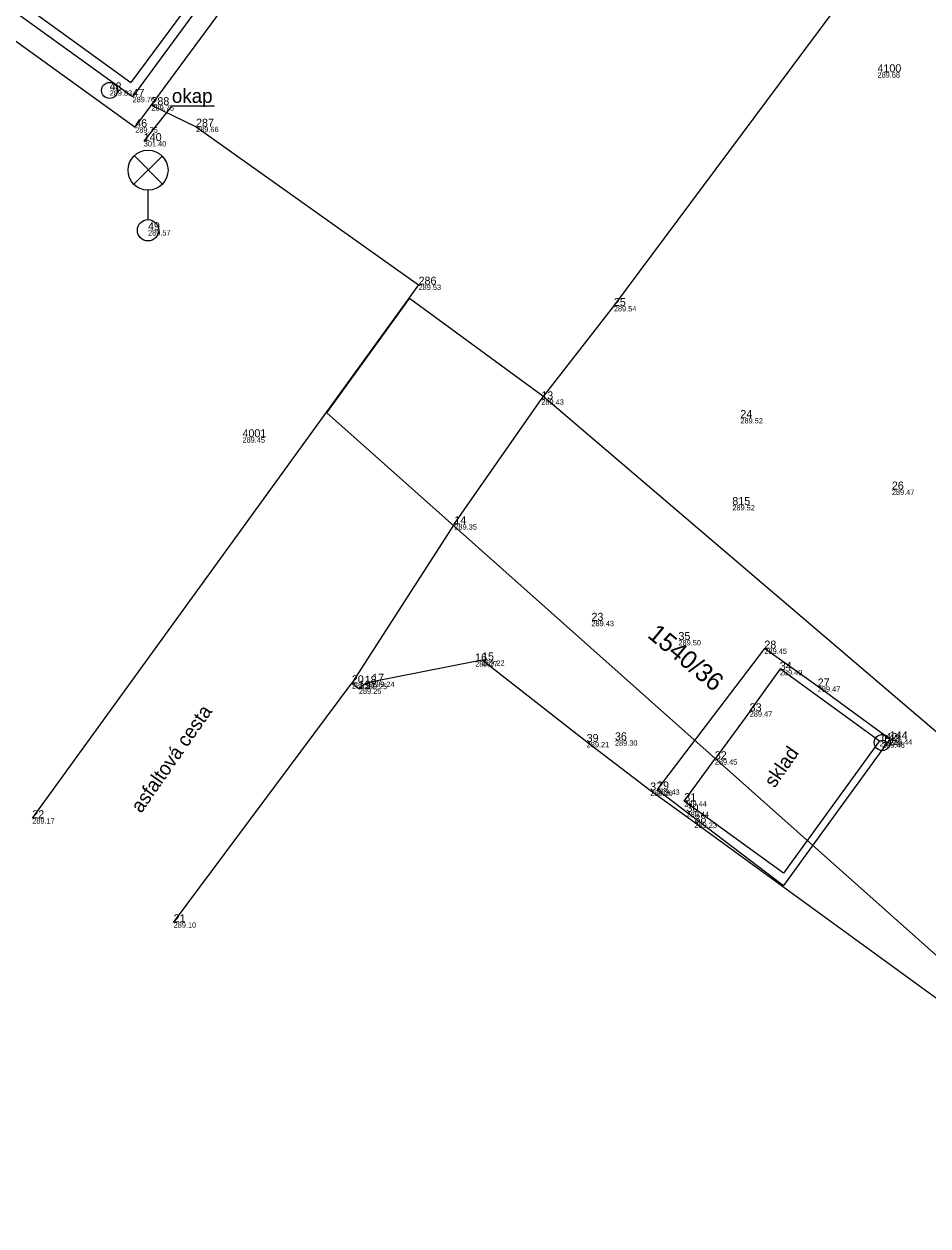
# Model space of a CAD drawing. Extents: x -805057 to -804930, y -994399 to -994240.
# Drawn here: x -804997.54 to -804980.6, y -994365.12 to -994342.6 of the extents above; entities that cross this region are included whole.
import ezdxf

# ---------------------------------------------------------------- set-up
doc = ezdxf.new("R2010")
doc.units = 0
for name, color, linetype in [('bod cislo', 7, 'Continuous'), ('bod pozice', 7, 'Continuous'), ('bod výška', 7, 'Continuous'), ('budova', 7, 'Continuous'), ('Katastralni mapa', 7, 'Continuous'), ('komunikace', 7, 'Continuous'), ('lampa', 7, 'Continuous'), ('plot', 7, 'Continuous'), ('popis', 7, 'Continuous'), ('svod', 7, 'Continuous')]:
    doc.layers.add(name, color=color, linetype=linetype)

msp = doc.modelspace()

# ---------------------------------------------------------------- linework, layer by layer
at = {"layer": 'bod pozice'}
for p, q in [((-804981.55, -994343.5), (-804981.55, -994343.5)), ((-804995.94, -994343.84), (-804995.94, -994343.84)), ((-804995.51, -994343.96), (-804995.51, -994343.96)), ((-804995.156, -994344.117), (-804995.156, -994344.117)), ((-804995.46, -994344.53), (-804995.46, -994344.53)), ((-804994.32, -994344.52), (-804994.32, -994344.52)), ((-804995.3, -994344.79), (-804995.3, -994344.79)), ((-804995.22, -994346.46), (-804995.22, -994346.46)), ((-804990.15, -994347.48), (-804990.15, -994347.48)), ((-804986.49, -994347.88), (-804986.49, -994347.88)), ((-804987.85, -994349.63), (-804987.85, -994349.63)), ((-804984.12, -994349.98), (-804984.12, -994349.98)), ((-804993.45, -994350.34), (-804993.45, -994350.34)), ((-804981.28, -994351.32), (-804981.28, -994351.32)), ((-804984.27, -994351.61), (-804984.27, -994351.61)), ((-804989.48, -994351.97), (-804989.48, -994351.97)), ((-804986.91, -994353.78), (-804986.91, -994353.78)), ((-804985.28, -994354.14), (-804985.28, -994354.14)), ((-804983.67, -994354.3), (-804983.67, -994354.3)), ((-804989.09, -994354.54), (-804989.09, -994354.54)), ((-804988.96, -994354.52), (-804988.96, -994354.52)), ((-804983.38, -994354.7), (-804983.38, -994354.7)), ((-804991.4, -994354.95), (-804991.4, -994354.95)), ((-804991.27, -994355.05), (-804991.27, -994355.05)), ((-804991.16, -994354.96), (-804991.16, -994354.96)), ((-804991.02, -994354.92), (-804991.02, -994354.92)), ((-804982.67, -994355.01), (-804982.67, -994355.01)), ((-804983.945, -994355.476), (-804983.945, -994355.476)), ((-804987, -994356.05), (-804987, -994356.05)), ((-804986.47, -994356.02), (-804986.47, -994356.02)), ((-804981.51, -994356.03), (-804981.51, -994356.03)), ((-804981.46, -994356.06), (-804981.46, -994356.06)), ((-804981.32, -994356), (-804981.32, -994356)), ((-804984.598, -994356.374), (-804984.598, -994356.374)), ((-804985.81, -994356.96), (-804985.81, -994356.96)), ((-804985.68, -994356.94), (-804985.68, -994356.94)), ((-804985.17, -994357.16), (-804985.17, -994357.16)), ((-804997.39, -994357.48), (-804997.39, -994357.48)), ((-804985.129, -994357.359), (-804985.129, -994357.359)), ((-804984.98, -994357.56), (-804984.98, -994357.56)), ((-804994.74, -994359.43), (-804994.74, -994359.43))]:
    msp.add_line(p, q, dxfattribs=at)
at = {"layer": 'budova'}
for p, q in [((-804995.51, -994343.96), (-805030.423, -994318.706)), ((-804991.63, -994338.67), (-804995.51, -994343.96)), ((-804983.945, -994355.476), (-804984.598, -994356.374))]:
    msp.add_line(p, q, dxfattribs=at)
msp.add_lwpolyline([(-804983.945, -994355.476), (-804983.366, -994354.68), (-804981.51, -994356.03), (-804983.314, -994358.51), (-804985.17, -994357.16), (-804984.598, -994356.374)], dxfattribs=at)
at = {"layer": 'Katastralni mapa'}
for points in [[(-805030.18, -994318.62), (-804995.54, -994343.69)], [(-804994.14, -994341.8), (-804995.54, -994343.69)], [(-804991.87, -994349.88), (-804990.32, -994347.74)], [(-804987.82, -994349.57), (-804990.32, -994347.74)], [(-804972.77, -994362.41), (-804987.82, -994349.57)], [(-804974.75, -994365.12), (-804991.87, -994349.88)]]:
    msp.add_lwpolyline(points, dxfattribs=at)
at = {"layer": 'komunikace'}
for p, q in [((-805005.97, -994336.96), (-804995.46, -994344.53)), ((-804995.46, -994344.53), (-804991.31, -994338.9)), ((-804986.49, -994347.88), (-804981.43, -994341.09)), ((-804995.156, -994344.117), (-804994.32, -994344.52)), ((-804994.32, -994344.52), (-804990.15, -994347.48)), ((-804990.15, -994347.48), (-804997.39, -994357.48)), ((-804987.85, -994349.63), (-804986.49, -994347.88)), ((-804989.48, -994351.97), (-804987.85, -994349.63)), ((-804989.48, -994351.97), (-804991.4, -994354.95)), ((-804983.67, -994354.3), (-804985.68, -994356.94)), ((-804982.67, -994355.01), (-804983.67, -994354.3)), ((-804994.74, -994359.43), (-804991.4, -994354.95)), ((-804991.4, -994354.95), (-804991.27, -994355.05)), ((-804991.27, -994355.05), (-804991.16, -994354.96)), ((-804981.32, -994356), (-804982.67, -994355.01)), ((-804981.32, -994356), (-804983.314, -994358.741)), ((-804985.68, -994356.94), (-804983.314, -994358.741))]:
    msp.add_line(p, q, dxfattribs=at)
at = {"layer": 'lampa'}
for p, q in [((-804995.484, -994345.598), (-804994.956, -994345.07)), ((-804994.948, -994345.595), (-804995.476, -994345.066)), ((-804995.22, -994346.26), (-804995.22, -994345.71))]:
    msp.add_line(p, q, dxfattribs=at)
for centre, radius in [((-804995.22, -994345.335), 0.375), ((-804995.22, -994346.46), 0.2)]:
    msp.add_circle(centre, radius, dxfattribs=at)
at = {"layer": 'plot'}
for p, q in [((-804989.09, -994354.54), (-804991.02, -994354.92)), ((-804988.96, -994354.52), (-804989.09, -994354.54)), ((-804987, -994356.05), (-804988.96, -994354.52)), ((-804991.02, -994354.92), (-804991.16, -994354.96)), ((-804985.81, -994356.96), (-804987, -994356.05)), ((-804984.98, -994357.56), (-804985.81, -994356.96)), ((-804976.67, -994363.6), (-804984.98, -994357.56))]:
    msp.add_line(p, q, dxfattribs=at)
at = {"layer": 'popis'}
for q in [(-804995.3, -994344.79), (-804993.974, -994344.126)]:
    msp.add_line((-804994.773, -994344.126), q, dxfattribs=at)
at = {"layer": 'svod'}
for centre in [(-804995.94, -994343.84), (-804981.46, -994356.06)]:
    msp.add_circle(centre, 0.15, dxfattribs=at)

# ---------------------------------------------------------------- texts
at = {"layer": 'bod cislo'}
for s, p in [('4100    ', (-804981.55, -994343.5)), ('48    ', (-804995.94, -994343.84)), ('47    ', (-804995.51, -994343.96)), ('288    ', (-804995.156, -994344.117)), ('46    ', (-804995.46, -994344.53)), ('287    ', (-804994.32, -994344.52)), ('140    ', (-804995.3, -994344.79)), ('49    ', (-804995.22, -994346.46)), ('286    ', (-804990.15, -994347.48)), ('25    ', (-804986.49, -994347.88)), ('13    ', (-804987.85, -994349.63)), ('24    ', (-804984.12, -994349.98)), ('4001    ', (-804993.45, -994350.34)), ('26    ', (-804981.28, -994351.32)), ('815    ', (-804984.27, -994351.61)), ('14    ', (-804989.48, -994351.97)), ('23    ', (-804986.91, -994353.78)), ('35    ', (-804985.28, -994354.14)), ('28    ', (-804983.67, -994354.3)), ('16    ', (-804989.09, -994354.54)), ('15    ', (-804988.96, -994354.52)), ('34    ', (-804983.38, -994354.7)), ('20    ', (-804991.4, -994354.95)), ('18    ', (-804991.16, -994354.96)), ('17    ', (-804991.02, -994354.92)), ('19    ', (-804991.27, -994355.05)), ('27    ', (-804982.67, -994355.01)), ('33    ', (-804983.945, -994355.476)), ('39    ', (-804987, -994356.05)), ('36    ', (-804986.47, -994356.02)), ('142    ', (-804981.51, -994356.03)), ('143    ', (-804981.46, -994356.06)), ('144    ', (-804981.32, -994356)), ('32    ', (-804984.598, -994356.374)), ('37    ', (-804985.81, -994356.96)), ('29    ', (-804985.68, -994356.94)), ('31    ', (-804985.17, -994357.16)), ('30    ', (-804985.129, -994357.359)), ('22    ', (-804997.39, -994357.48)), ('38    ', (-804984.98, -994357.56)), ('21    ', (-804994.74, -994359.43))]:
    msp.add_text(s, height=0.15, dxfattribs=at).set_placement(p)
at = {"layer": 'bod výška'}
for s, p in [('289.68  ', (-804981.55, -994343.6)), ('289.83  ', (-804995.94, -994343.94)), ('289.76  ', (-804995.51, -994344.06)), ('289.75  ', (-804995.156, -994344.217)), ('289.75  ', (-804995.46, -994344.63)), ('289.66  ', (-804994.32, -994344.62)), ('301.40  ', (-804995.3, -994344.89)), ('289.57  ', (-804995.22, -994346.56)), ('289.53  ', (-804990.15, -994347.58)), ('289.54  ', (-804986.49, -994347.98)), ('289.43  ', (-804987.85, -994349.73)), ('289.52  ', (-804984.12, -994350.08)), ('289.45  ', (-804993.45, -994350.44)), ('289.47  ', (-804981.28, -994351.42)), ('289.52  ', (-804984.27, -994351.71)), ('289.35  ', (-804989.48, -994352.07)), ('289.43  ', (-804986.91, -994353.88)), ('289.50  ', (-804985.28, -994354.24)), ('289.45  ', (-804983.67, -994354.4)), ('289.27  ', (-804989.09, -994354.64)), ('289.22  ', (-804988.96, -994354.62)), ('289.49  ', (-804983.38, -994354.8)), ('289.24  ', (-804991.4, -994355.05)), ('289.25  ', (-804991.27, -994355.15)), ('289.25  ', (-804991.16, -994355.06)), ('289.24  ', (-804991.02, -994355.02)), ('289.47  ', (-804982.67, -994355.11)), ('289.47  ', (-804983.945, -994355.576)), ('289.21  ', (-804987, -994356.15)), ('289.30  ', (-804986.47, -994356.12)), ('289.46  ', (-804981.51, -994356.13)), ('289.46  ', (-804981.46, -994356.16)), ('289.44  ', (-804981.32, -994356.1)), ('289.45  ', (-804984.598, -994356.474)), ('289.26  ', (-804985.81, -994357.06)), ('289.43  ', (-804985.68, -994357.04)), ('289.44  ', (-804985.17, -994357.26)), ('289.17  ', (-804997.39, -994357.58)), ('289.44  ', (-804985.129, -994357.459)), ('289.23  ', (-804984.98, -994357.66)), ('289.10  ', (-804994.74, -994359.53))]:
    msp.add_text(s, height=0.1, dxfattribs=at).set_placement(p)
at = {"layer": 'Katastralni mapa'}
msp.add_text('1540/36', height=0.34, rotation=320.4025, dxfattribs=at).set_placement((-804985.879, -994354.074))
at = {"layer": 'popis'}
msp.add_text('okap', height=0.2629, dxfattribs=at).set_placement((-804994.773, -994344.073))
for s, height, p in [('asfaltová cesta', 0.26289, (-804995.348, -994357.398)), ('sklad', 0.2629, (-804983.479, -994356.925))]:
    msp.add_text(s, height=height, rotation=55.131, dxfattribs=at).set_placement(p)

doc.saveas('drawing.dxf')
